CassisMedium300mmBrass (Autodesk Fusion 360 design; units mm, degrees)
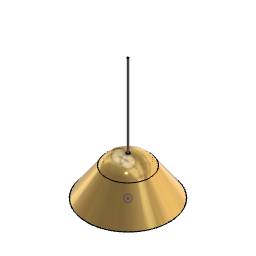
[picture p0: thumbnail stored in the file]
sketch "Sketch1" plane through (0, 0, 0) normal (0, 1, 0) x axis (1, 0, 0)
  line L1 (-5, -140) -> (0, -140)
  line L2 (-77.9023, -102.6) -> (-150, 0)
  line L3 (0, 0) -> (0, -140)
  line L4 (-150, 0) -> (0, 0)
  arc A1 centre (-5.9016, -52.0046) radius 88 clockwise from (-5, -140) to (-77.9023, -102.6)
  point P1 (0, 0)
  point P4 (-150, 0)
  point P2 (0, -140)
  point P7 (0, 0)
  point P3 (-5, -140)
  point P5 (-77.9023, -102.6)
  horizontal L1
  horizontal P1 P4
  vertical P1 P2
  coincident P1 P7
  tangent L2 A1
  dimension "d1" distance P2 P3 = 5
  dimension "d2" distance P1 L1 = 140
  dimension "d3" distance P1 P4 = 150
  dimension "d39" distance P5 L4 = 102.6
  dimension "d40" radius A1 = 88
revolve "Revolve1" sketch "Sketch1" AlongAngle 360
shell "Shell1" innerThickness 1.5
fillet "Fillet1" radius 0.5
sketch "Sketch2" plane through (0, 0, 0) normal (0, 1, 0) x axis (1, 0, 0)
  line L1 (-32.2676, -115) -> (0, -115)
  point P1 (0, 0)
  horizontal L1
  dimension "d14" distance P1 L1 = 115
work_plane "WorkPlane1" AlongDistance 70
sketch "Sketch4" plane through (0, 0, 115) normal (0, 0, 1) x axis (1, 0, 0)
  circle C1 centre (0, 0) radius 43.7102
  point P1 (0, 0)
  point P2 (0, 0)
  coincident P1 P2
extrude "Extrude2" new body sketch "Sketch4" against normal blind 12 taper -20
sketch "Sketch8" plane through (0, 0, 115) normal (0, 0, 1) x axis (-1, 0, 0)
  circle C1 centre (0, 0) radius 43.7102
  circle C2 centre (0, 0) radius 62.5
  point P1 (0, 0)
  point P3 (0, 0)
  coincident P1 P3
  dimension "d41" diameter C2 = 125
extrude "Extrude8" new body sketch "Sketch8" along normal blind 1
sketch "Sketch5" plane through (0, 0, 103) normal (0, 0, -1) x axis (1, 0, 0)
  circle C1 centre (0, 0) radius 39.3425
  circle C2 centre (0, 0) radius 35.3425
  point P1 (0, 0)
  point P3 (0, 0)
  coincident P1 P3
  dimension "d19" distance C1 C2 = 4
extrude "Extrude3" cut sketch "Sketch5" profile of C2 against normal blind 10
extrude "Extrude4" new body of existing geometry blind 20
work_plane "WorkPlane2" AlongDistance -5
split "Split1"
fillet "Fillet2" radius 0.1
fillet "Fillet3" radius 0.4
sketch "Sketch6" plane through (0, 0, 140) normal (0, 0, 1) x axis (-1, 0, 0)
  circle C1 centre (0, 0) radius 5
  circle C2 centre (0, 0) radius 6
  point P1 (0, 0)
  point P3 (0, 0)
  coincident P1 P3
  dimension "d29" diameter C2 = 12
extrude "Extrude5" new body sketch "Sketch6" along normal blind 1.5
extrude "Extrude6" cut of existing geometry blind -1.5
sketch "Sketch7" plane through (0, 0, 115) normal (0, 0, 1) x axis (-1, 0, 0)
  circle C1 centre (0, 0) radius 43.7102
  circle C2 centre (0, 0) radius 3
  point P1 (0, 0)
  point P3 (0, 0)
  coincident P1 P3
  dimension "d34" diameter C2 = 6
extrude "Extrude7" new body sketch "Sketch7" profile of C2 along normal blind 323
fillet "Fillet4" radius 0.2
